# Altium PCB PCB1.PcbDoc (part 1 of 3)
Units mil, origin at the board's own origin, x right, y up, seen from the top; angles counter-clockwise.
Board outline 3586 x 4364 mil, 2 copper layers (Top Layer, Bottom Layer); 0 components, 57 nets, 205 pads, 0 vias.
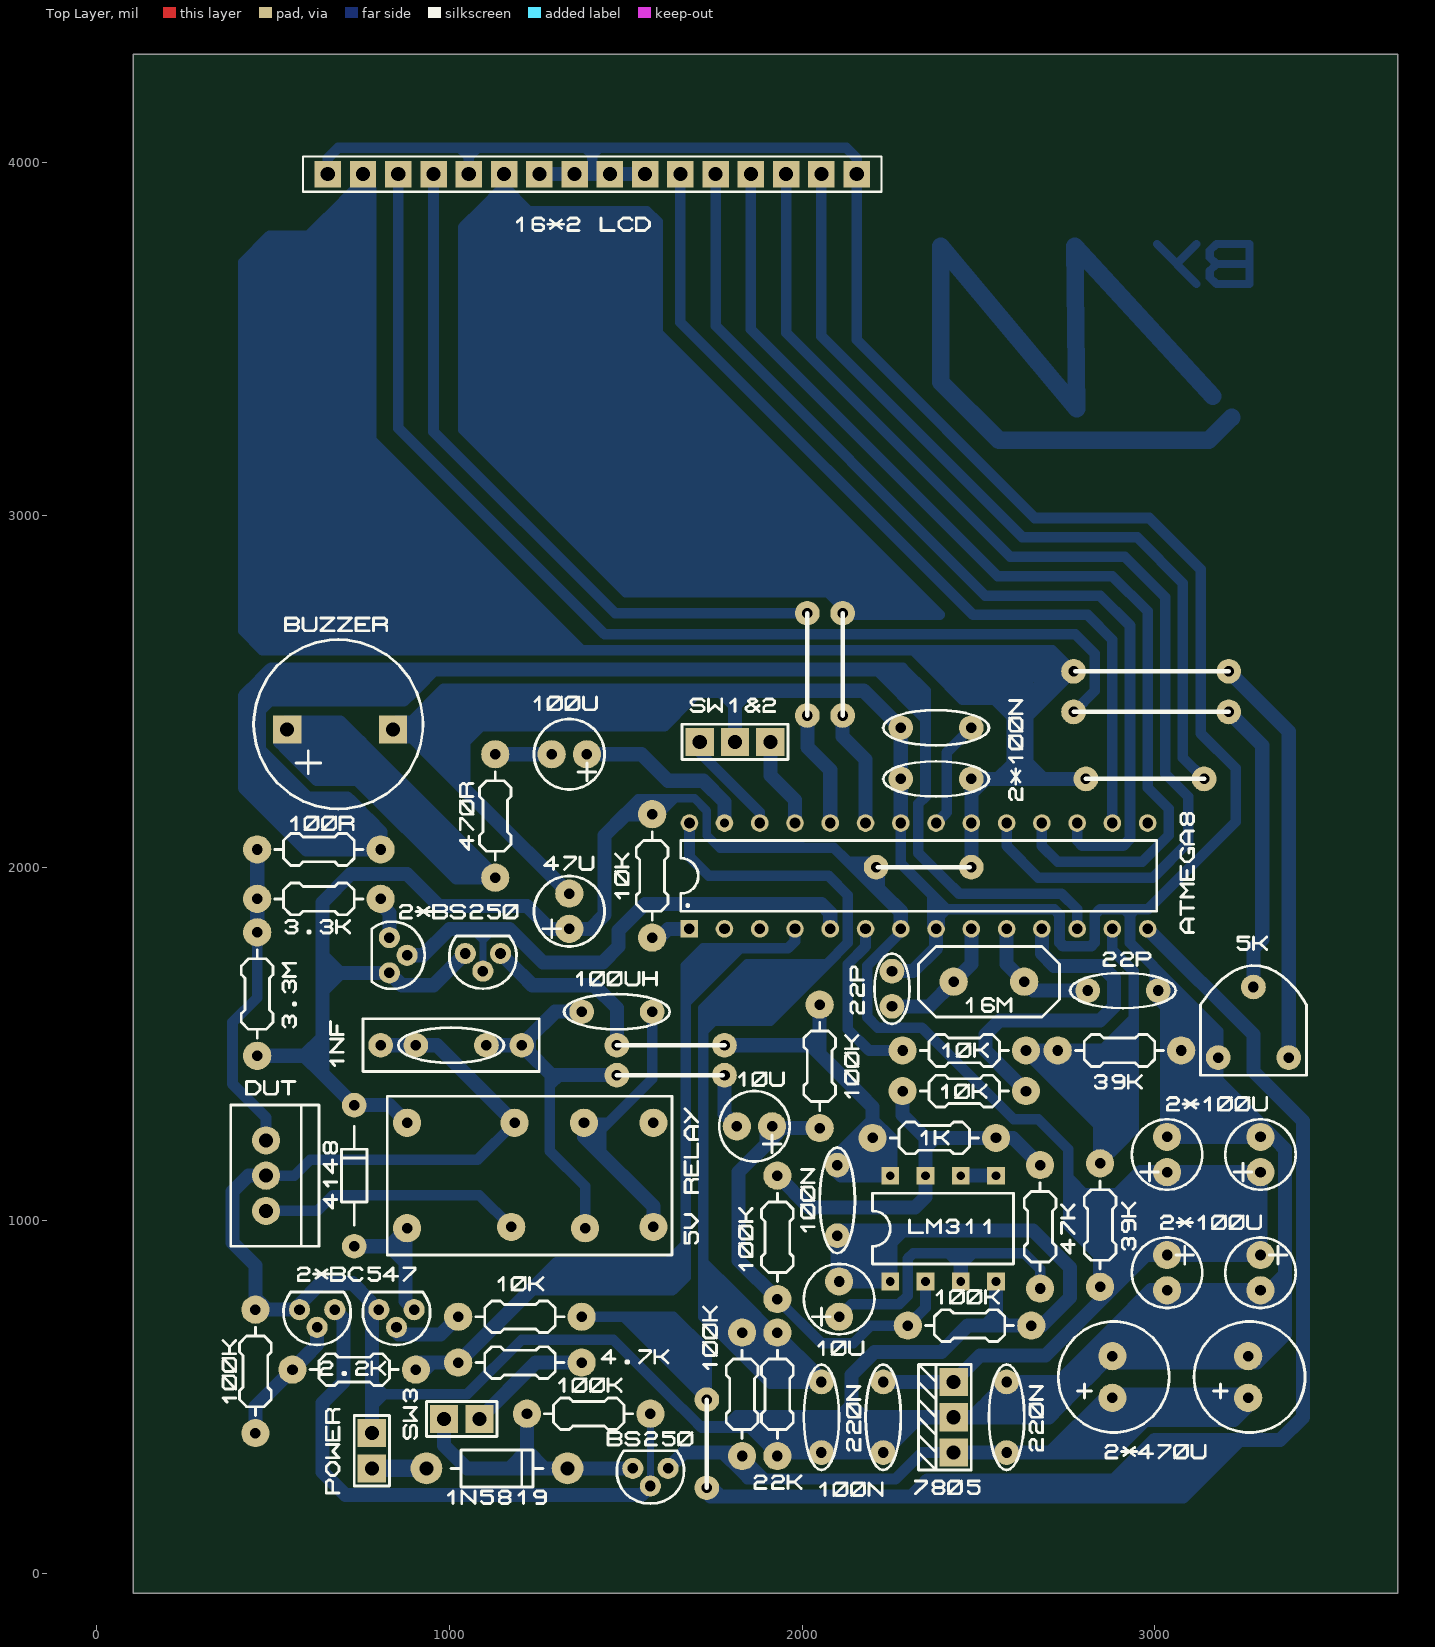
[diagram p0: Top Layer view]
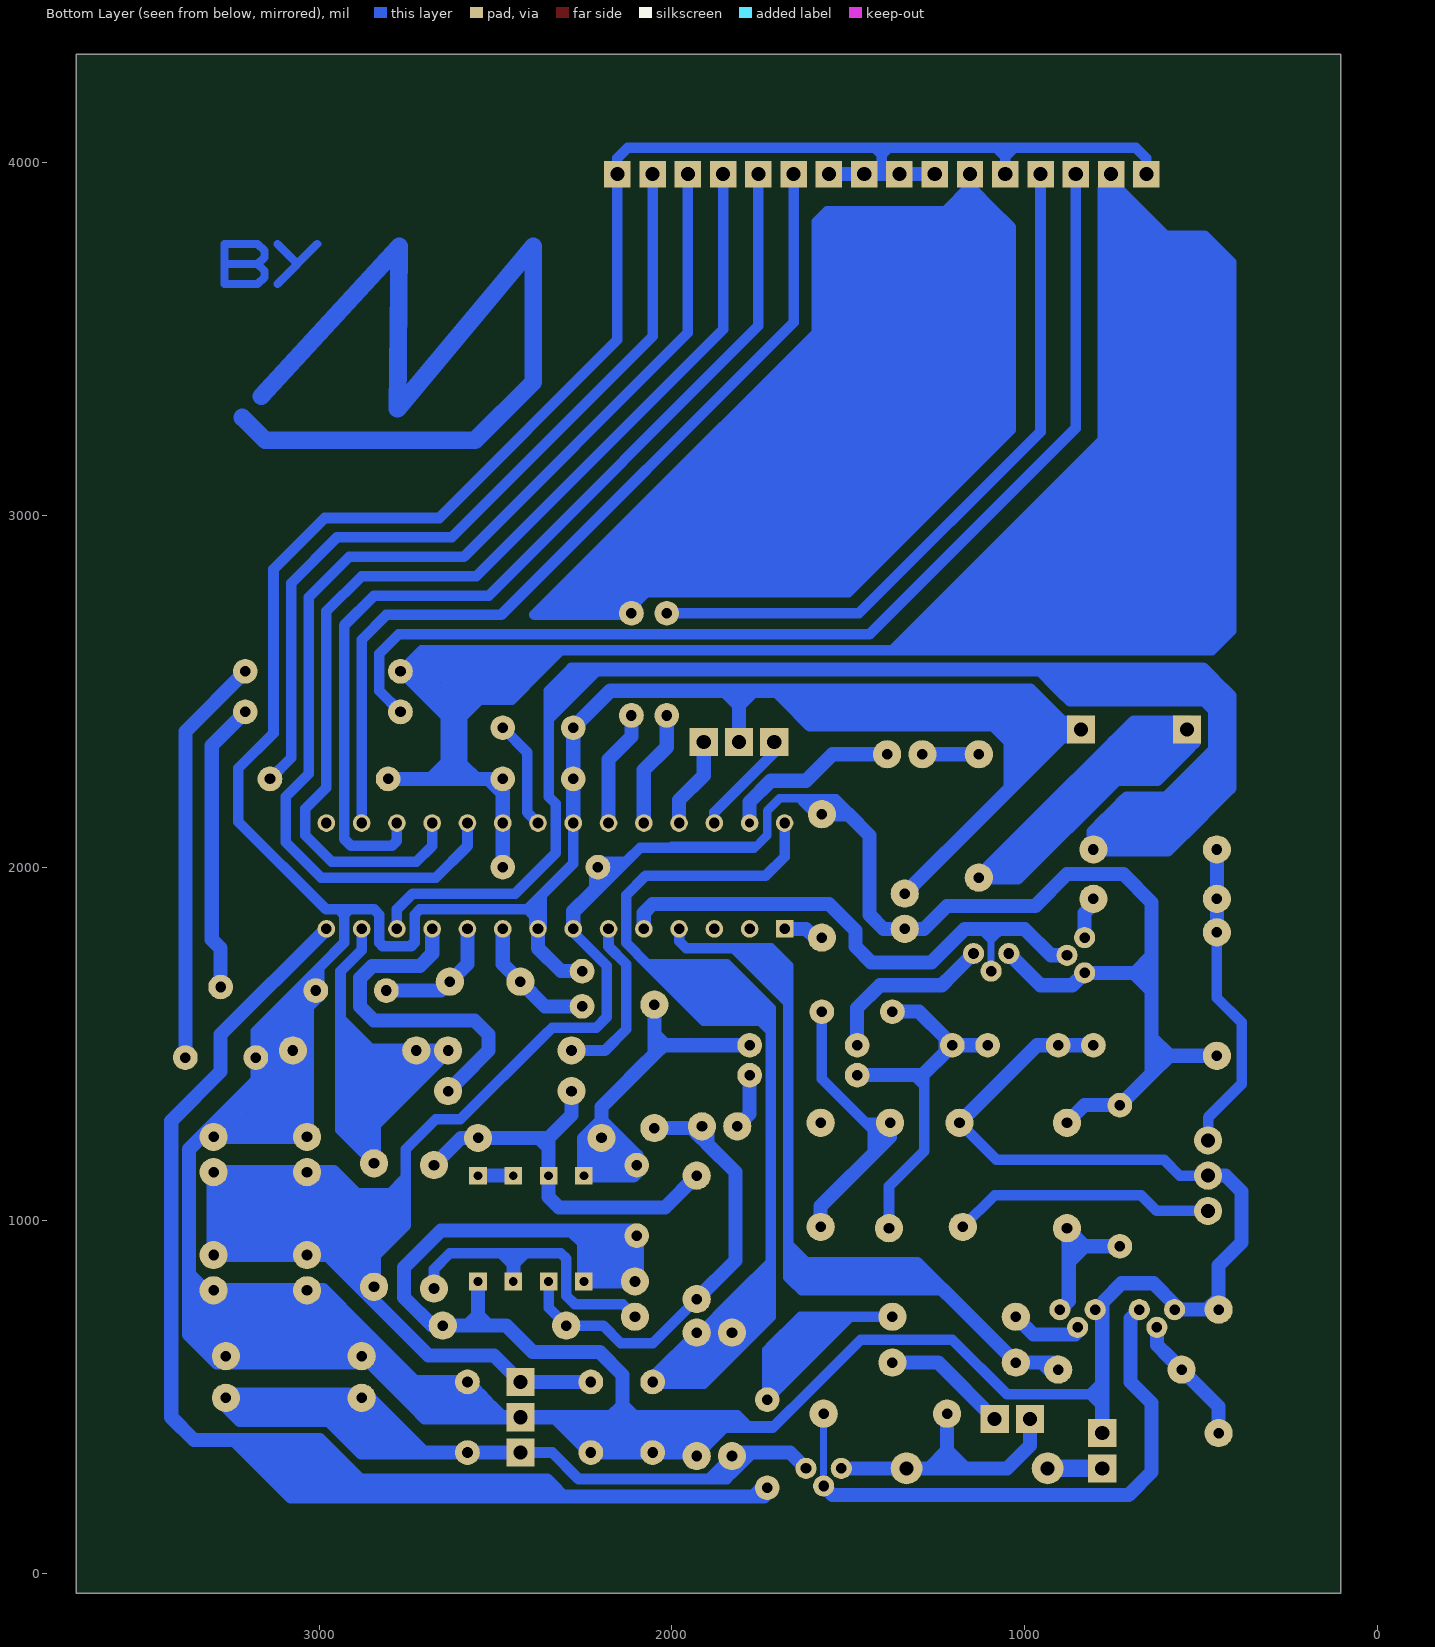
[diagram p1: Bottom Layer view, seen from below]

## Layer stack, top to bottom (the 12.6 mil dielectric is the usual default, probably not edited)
Top Layer: signal copper 1.4
Dielectric: dielectric 12.6, FR-4, Dk 4.8
Bottom Layer: signal copper 1.4

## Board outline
103,-57 3689,-57 3689,4307 103,4307

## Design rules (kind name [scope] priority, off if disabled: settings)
Clearance CAM_Clearance_2 [OnLayer('Top Layer')] p1: gap=10.71
Clearance CAM_Clearance_1 [OnLayer('Bottom Layer')] p2: gap=10
Clearance [All] p3: gap=10
PolygonConnect [All] p1: connectstyle=Relief reliefconductorwidth=10 reliefentries=4 polygonreliefangle="90 Angle"
RoutingVias [All] p1: holewidth=28 width=50 viastyle="Through Hole" minholewidth=28 minwidth=50 maxholewidth=28 maxwidth=50
SilkscreenOverComponentPads [All] p1: minsilkscreentomaskgap=10
SolderMaskExpansion [All] p1: expansion=4
Width CAM_Width_1 [OnLayer('Bottom Layer')] p1: maxlimit=101 minlimit=19 preferedwidth=20
Width [All] p2: maxlimit=10 minlimit=10 preferedwidth=10
27 further rules are at their usual default settings.

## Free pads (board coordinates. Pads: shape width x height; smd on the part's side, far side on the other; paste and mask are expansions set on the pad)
  round 60 hole 118.1: 1(0,0) 1(0,0) 1(0,0) 1(0,0)
  round 80 hole 30: 1(449.35,396.74) 1(449.35,746.74) 1(454.35,1466.74) 1(454.35,1816.74) 1(454.35,1911.74) 1(454.35,2051.74) 1(554.35,576.74) 1(804.35,1911.74) 1(804.35,2051.74) 1(879.35,977.74) 1(879.35,1276.74) 1(904.35,576.74) 1(1024.35,596.74) 1(1024.35,726.74) 1(1129.35,1971.74) 1(1129.35,2321.74) 1(1174.65,981.54) 1(1184.15,1276.74) 1(1219.35,451.74) 1(1289.35,2321.74) 1(1339.35,1826.74) 1(1339.35,1926.74) 1(1374.35,596.74) 1(1374.35,726.74) 1(1380.95,1276.74) 1(1384.15,977.74) 1(1389.35,2321.74) 1(1569.35,451.74) 1(1574.35,1801.74) 1(1574.35,2151.74) 1(1577.85,981.54) 1(1577.85,1276.74) 1(1814.35,1266.74) 1(1829.35,331.74) 1(1829.35,681.74) 1(1914.35,1266.74) 1(1929.35,331.74) 1(1929.35,681.74) 1(1929.35,776.74) 1(1929.35,1126.74) 1(2049.35,1261.74) 1(2049.35,1611.74) 1(2104.35,726.74) 1(2104.35,826.74) 1(2199.35,1233.74) 1(2284.35,1366.74) 1(2284.35,1481.74) 1(2299.35,701.74) 1(2429.35,1676.74) 1(2549.35,1233.74) 1(2629.35,1676.74) 1(2634.35,1366.74) 1(2634.35,1481.74) 1(2649.35,701.74) 1(2674.35,806.74) 1(2674.35,1156.74) 1(2724.35,1481.74) 1(2844.35,811.74) 1(2844.35,1161.74) 1(2879.35,496.74) 1(2879.35,614.94) 1(3034.35,801.74) 1(3034.35,901.74) 1(3034.35,1136.74) 1(3034.35,1236.74) 1(3074.35,1481.74) 1(3264.35,496.74) 1(3264.35,614.94) 1(3299.35,801.74) 1(3299.35,901.74) 1(3299.35,1136.74) 1(3299.35,1236.74)
  round 80 hole 40: 1(479.35,1026.74) 1(479.35,1126.74) 1(479.35,1226.74)
  rect 80x80 hole 40: 1(539.35,2391.74) 1(779.35,296.74) 1(779.35,396.74) 1(839.35,2391.74) 1(984.35,436.74) 1(1084.35,436.74) 1(1709.35,2356.74) 1(1809.35,2356.74) 1(1909.35,2356.74) 1(2429.35,341.74) 1(2429.35,441.74) 1(2429.35,541.74)
  round 60 hole 30: 1(574.35,746.74) 1(624.35,696.74) 1(674.35,746.74) 1(799.35,746.74) 1(829.35,1701.74) 1(829.35,1801.74) 1(849.35,696.74) 1(879.35,1751.74) 1(899.35,746.74) 1(1044.35,1756.74) 1(1094.35,1706.74) 1(1144.35,1756.74) 1(1519.35,296.74) 1(1569.35,246.74) 1(1619.35,296.74)
  rect 75x75 hole 40: 1(654.35,3966.74) 1(754.35,3966.74) 1(854.35,3966.74) 1(954.35,3966.74) 1(1054.35,3966.74) 1(1154.35,3966.74) 1(1254.35,3966.74) 1(1354.35,3966.74) 1(1454.35,3966.74) 1(1554.35,3966.74) 1(1654.35,3966.74) 1(1754.35,3966.74) 1(1854.35,3966.74) 1(1954.35,3966.74) 1(2054.35,3966.74) 1(2154.35,3966.74)
  round 70 hole 30: 1(729.35,926.74) 1(729.35,1326.74) 1(804.35,1496.74) 1(904.35,1496.74) 1(1104.35,1496.74) 1(1204.35,1496.74) 1(1374.35,1591.74) 1(1474.35,1411.74) 1(1474.35,1496.74) 1(1574.35,1591.74) 1(1729.35,241.74) 1(1729.35,491.74) 1(1779.35,1411.74) 1(1779.35,1496.74) 1(2014.35,2431.74) 1(2014.35,2721.74) 1(2054.35,341.74) 1(2054.35,541.74) 1(2099.35,956.74) 1(2099.35,1156.74) 1(2114.35,2431.74) 1(2114.35,2721.74) 1(2209.35,2001.74) 1(2229.35,341.74) 1(2229.35,541.74) 1(2254.35,1606.74) 1(2254.35,1706.74) 1(2279.35,2251.74) 1(2279.35,2396.74) 1(2479.35,2001.74) 1(2479.35,2251.74) 1(2479.35,2396.74) 1(2579.35,341.74) 1(2579.35,541.74) 1(2769.35,2441.74) 1(2769.35,2556.74) 1(2804.35,2251.74) 1(2809.35,1651.74) 1(3009.35,1651.74) 1(3139.35,2251.74) 1(3179.35,1461.74) 1(3209.35,2441.74) 1(3209.35,2556.74) 1(3279.35,1661.74) 1(3379.35,1461.74)
  round 90 hole 40: 1(934.35,296.74) 1(1334.35,296.74)
  rect 50x50 hole 30: 1(1679.35,1826.74)
  round 50 hole 30: 1(1680.15,2126.74) 1(1779.35,1826.74) 1(1879.35,1826.74) 1(1879.35,2126.74) 1(1979.35,1826.74) 1(1979.35,2126.74) 1(2079.35,1826.74) 1(2079.35,2126.74) 1(2179.35,1826.74) 1(2179.35,2126.74) 1(2279.35,1826.74) 1(2279.35,2126.74) 1(2379.35,1826.74) 1(2379.35,2126.74) 1(2479.35,1826.74) 1(2479.35,2126.74) 1(2579.35,1826.74) 1(2579.35,2126.74) 1(2679.35,1826.74) 1(2679.35,2126.74) 1(2779.35,1826.74) 1(2779.35,2126.74) 1(2879.35,1826.74) 1(2879.35,2126.74) 1(2979.35,1826.74) 1(2979.35,2126.74)
  round 50 hole 25: 1(1779.35,2126.74)
  rect 50x50 hole 25: 1(2249.35,826.74) 1(2249.35,1126.74) 1(2349.35,826.74) 1(2349.35,1126.74) 1(2449.35,826.74) 1(2449.35,1126.74) 1(2549.35,826.74) 1(2549.35,1126.74)

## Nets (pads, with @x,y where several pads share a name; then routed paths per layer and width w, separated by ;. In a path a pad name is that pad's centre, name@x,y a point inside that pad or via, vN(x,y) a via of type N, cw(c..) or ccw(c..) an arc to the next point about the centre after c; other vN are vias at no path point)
$Net0: pad.1@449.35,746.74 pad.1@479.35,1126.74 pad.1@574.35,746.74 pad.1@654.35,3966.74 pad.1@779.35,396.74 pad.1@799.35,746.74 pad.1@804.35,1496.74 pad.1@839.35,2391.74 pad.1@904.35,1496.74 pad.1@1054.35,3966.74 pad.1@1184.15,1276.74 pad.1@1254.35,3966.74 pad.1@1339.35,1926.74 pad.1@1354.35,3966.74 pad.1@1454.35,3966.74 pad.1@1554.35,3966.74 pad.1@1809.35,2356.74 pad.1@1929.35,331.74 pad.1@2054.35,341.74 pad.1@2099.35,956.74 pad.1@2104.35,826.74 pad.1@2154.35,3966.74 pad.1@2229.35,341.74 pad.1@2249.35,826.74 pad.1@2254.35,1706.74 pad.1@2279.35,2126.74 pad.1@2279.35,2251.74 pad.1@2279.35,2396.74 pad.1@2379.35,1826.74 pad.1@2429.35,441.74 pad.1@2549.35,826.74 pad.1@2579.35,541.74 pad.1@2649.35,701.74 pad.1@2879.35,614.94 pad.1@3009.35,1651.74 pad.1@3034.35,801.74 pad.1@3034.35,1236.74 pad.1@3074.35,1481.74 pad.1@3179.35,1461.74 pad.1@3264.35,614.94 pad.1@3299.35,801.74 pad.1@3299.35,1236.74 | length 40989.2
  Bottom Layer w20: pad.1@2364.35,1831.74 2364.35,1851.74 ; 2364.35,1926.74 2364.35,1886.74 2364.35,1851.74 ; pad.1@2379.35,1826.74 2364.35,1851.74 ; pad.1@2394.35,1831.74 2394.35,1841.74 2394.35,1856.74 2394.35,1866.74 ; 2734.35,1791.74 2744.35,1781.74 2749.35,1776.74 2754.35,1771.74 ; 2814.35,1781.74 2829.35,1796.74
  Bottom Layer w30: pad.1@449.35,746.74 449.35,786.74 489.35,746.74 494.35,741.74 ; pad.1@479.35,1126.74 559.35,1126.74 604.35,1171.74 1079.15,1171.74 pad.1@1184.15,1276.74 ; pad.1@654.35,3966.74 654.35,4011.74 671.85,4029.24 684.35,4041.74 764.35,4041.74 854.35,4041.74 1029.35,4041.74 ; 774.35,691.74 774.35,771.74 pad.1@799.35,746.74 ; 779.35,471.74 814.35,506.74 ; 779.35,541.74 814.35,506.74 ; 1024.35,2401.74 1039.35,2401.74 1054.35,2401.74 1069.35,2401.74 ; 1034.35,2366.74 1039.35,2371.74 1069.35,2401.74 ; 1039.35,2351.74 1089.35,2401.74 ; pad.1@1054.35,3966.74 1054.35,4016.74 ; 1109.35,2426.74 1114.35,2426.74 ; 1129.35,2461.74 1099.35,2431.74 1069.35,2401.74 ; 1154.35,2466.74 1119.35,2431.74 1114.35,2426.74 ; 1174.35,2436.74 1204.35,2436.74 1213.35,2436.74 1234.35,2436.74 ; 1254.35,2441.74 1284.35,2471.74 ; 1259.35,2441.74 1284.35,2441.74 ; 1259.35,2471.74 1269.35,2471.74 ; 1284.35,2421.74 1294.35,2421.74 ; 1299.35,2501.74 1269.35,2471.74 ; 1314.35,2501.74 1284.35,2471.74 ; 1334.35,2491.74 1314.35,2471.74 ; 1374.35,2501.74 1344.35,2471.74 ; pad.1@1374.35,3966.74 1404.35,3996.74 ; 1404.35,3966.74 1404.35,3996.74 ; pad.1@1434.35,3966.74 1404.35,3996.74 ; 1579.35,2501.74 1549.35,2471.74 ; 1624.35,2421.74 1499.35,2421.74 ; 1634.35,2441.74 1519.35,2441.74 ; 1661.85,2461.74 1539.35,2461.74 ; 1709.35,2501.74 1679.35,2471.74 ; 1804.35,426.74 2084.35,426.74 ; 1859.35,406.74 1874.35,391.74 ; 1859.35,416.74 1844.35,416.74 ; 1869.35,406.74 1884.35,391.74 ; 1879.35,446.74 1814.35,446.74 1784.35,416.74 ; pad.1@1934.35,326.74 pad.1@1929.35,331.74 1869.35,391.74 ; pad.1@1934.35,331.74 1929.35,336.74 1874.35,391.74 ; pad.1@1934.35,341.74 pad.1@1929.35,346.74 ; 1939.35,371.74 1979.35,371.74 ; pad.1@1954.35,336.74 pad.1@1944.35,346.74 ; 2009.35,341.74 2004.35,346.74 ; 2019.35,346.74 2004.35,346.74 ; 2039.35,381.74 2049.35,391.74 ; 2114.35,371.74 pad.1@2064.35,371.74 ; 2139.35,391.74 2084.35,391.74 ; 2139.35,446.74 2134.35,441.74 2119.35,426.74 ; 2254.35,366.74 2224.35,396.74 2204.35,416.74 2194.35,426.74 ; 2264.35,426.74 2194.35,426.74 ; pad.1@2279.35,2136.74 pad.1@2279.35,2126.74 2279.35,2011.74 2284.35,2006.74 2324.35,1966.74 2364.35,1926.74 2379.35,1911.74 ; pad.1@2379.35,1826.74 2379.35,1851.74 ; 2514.35,701.74 2549.35,736.74 ; 2549.35,701.74 2549.35,736.74 ; 2584.35,701.74 2549.35,736.74 ; 2999.35,1696.74 2999.35,1716.74 ; 3059.35,1581.74 3074.35,1566.74 3079.35,1561.74 ; 3174.35,1511.74 3044.35,1641.74 pad.1@3009.35,1651.74 3009.35,1706.74 ; 3179.35,1391.74 pad.1@3179.35,1461.74 3179.35,1481.74 3179.35,1536.74 3174.35,1541.74 3164.35,1551.74 3009.35,1706.74 ; 814.35,506.74 1049.35,506.74 1204.35,661.74 1369.35,661.74 1429.35,661.74 1464.35,661.74 1579.35,546.74 1624.35,501.74 1691.85,434.24 1709.35,416.74 ; 1029.35,4041.74 1054.35,4041.74 ; 1029.35,4041.74 1054.35,4016.74 ; 1054.35,4016.74 1054.35,4041.74 ; 1054.35,4016.74 1079.35,4041.74 ; 1054.35,4041.74 1079.35,4041.74 ; 1069.35,2401.74 1089.35,2401.74 ; 1079.35,4041.74 1084.35,4041.74 1119.35,4041.74 1154.35,4041.74 1164.35,4041.74 1184.35,4041.74 1224.35,4041.74 1384.35,4041.74 ; 1089.35,2401.74 1214.35,2401.74 1274.35,2401.74 ; 1089.35,2401.74 1114.35,2426.74 ; 1114.35,2426.74 1209.35,2426.74 1224.35,2426.74 ; 1224.35,2426.74 1229.35,2431.74 ; 1224.35,2426.74 1299.35,2426.74 ; 1229.35,2431.74 1234.35,2431.74 ; 1229.35,2431.74 1234.35,2436.74 ; 1229.35,2431.74 1209.35,2431.74 1179.35,2431.74 1169.35,2431.74 1234.35,2431.74 ; 1234.35,2431.74 1294.35,2431.74 ; 1234.35,2436.74 1269.35,2471.74 ; 1234.35,2436.74 1279.35,2436.74 ; 1269.35,2471.74 1284.35,2471.74 ; 1274.35,2401.74 1479.35,2401.74 ; 1274.35,2401.74 1294.35,2421.74 ; 1279.35,2436.74 1284.35,2441.74 ; 1279.35,2436.74 1299.35,2436.74 ; 1284.35,2441.74 1314.35,2471.74 ; 1284.35,2441.74 1304.35,2441.74 ; 1284.35,2471.74 1314.35,2471.74 ; 1294.35,2421.74 1499.35,2421.74 ; 1294.35,2421.74 1299.35,2426.74 ; 1294.35,2431.74 1299.35,2436.74 ; 1294.35,2431.74 1304.35,2431.74 ; 1299.35,2426.74 1304.35,2431.74 ; 1299.35,2436.74 1309.35,2436.74 ; 1299.35,2436.74 1304.35,2441.74 ; 1304.35,2431.74 1309.35,2436.74 ; 1304.35,2441.74 1314.35,2441.74 ; 1309.35,2436.74 1314.35,2441.74 ; 1314.35,2441.74 1519.35,2441.74 ; 1314.35,2441.74 1319.35,2446.74 1324.35,2451.74 1334.35,2461.74 ; 1314.35,2471.74 1344.35,2471.74 ; 1334.35,2461.74 1539.35,2461.74 ; 1334.35,2461.74 1344.35,2471.74 ; 1344.35,2471.74 1549.35,2471.74 ; 1384.35,4041.74 1404.35,4021.74 ; 1384.35,4041.74 1404.35,4041.74 ; 1404.35,3996.74 1404.35,4001.74 1404.35,4006.74 1404.35,4021.74 ; 1404.35,4021.74 1404.35,4041.74 ; 1404.35,4021.74 1424.35,4041.74 ; 1404.35,4041.74 1424.35,4041.74 ; 1424.35,4041.74 1454.35,4041.74 1474.35,4041.74 2009.35,4041.74 2069.35,4041.74 2124.35,4041.74 2154.35,4011.74 2154.35,3976.74 pad.1@2154.35,3966.74 2154.35,3496.74 2659.35,2991.74 2984.35,2991.74 3129.35,2846.74 3129.35,2381.74 3229.35,2281.74 3229.35,2130.74 2980.35,1881.74 2944.35,1881.74 ; 1479.35,2401.74 1594.35,2401.74 1609.35,2401.74 1679.35,2471.74 ; 1479.35,2401.74 1499.35,2421.74 ; 1499.35,2421.74 1519.35,2441.74 ; 1519.35,2441.74 1539.35,2461.74 ; 1539.35,2461.74 1549.35,2471.74 ; 1549.35,2471.74 1679.35,2471.74 ; 1709.35,416.74 1714.35,411.74 1794.35,411.74 1829.35,411.74 1844.35,411.74 ; 1709.35,416.74 1784.35,416.74 ; 1784.35,416.74 1844.35,416.74 ; 1844.35,411.74 1849.35,411.74 ; 1844.35,411.74 1844.35,416.74 ; 1844.35,416.74 1849.35,411.74 ; 1849.35,411.74 2069.35,411.74 ; 1849.35,411.74 1869.35,391.74 ; 1869.35,391.74 1874.35,391.74 ; 1874.35,391.74 1884.35,391.74 ; 1884.35,391.74 1899.35,391.74 ; 1884.35,391.74 pad.1@1924.35,351.74 ; 1899.35,391.74 1959.35,391.74 ; 1899.35,391.74 pad.1@1924.35,366.74 ; pad.1@1924.35,346.74 pad.1@1924.35,351.74 ; pad.1@1924.35,346.74 1929.35,341.74 pad.1@1929.35,346.74 ; pad.1@1924.35,346.74 pad.1@1929.35,346.74 ; pad.1@1924.35,351.74 pad.1@1924.35,366.74 ; pad.1@1924.35,351.74 pad.1@1929.35,346.74 ; pad.1@1924.35,366.74 pad.1@1944.35,346.74 ; pad.1@1929.35,346.74 pad.1@1944.35,346.74 ; pad.1@1944.35,346.74 2004.35,346.74 ; 1959.35,391.74 2049.35,391.74 ; 1959.35,391.74 1979.35,371.74 ; 1979.35,371.74 pad.1@2064.35,371.74 ; 1979.35,371.74 2004.35,346.74 ; 2049.35,391.74 2069.35,411.74 ; 2049.35,391.74 2084.35,391.74 ; pad.1@2064.35,371.74 2084.35,391.74 ; 2069.35,411.74 2084.35,426.74 ; 2084.35,391.74 2119.35,426.74 ; 2084.35,426.74 2099.35,441.74 2139.35,481.74 2179.35,441.74 2194.35,426.74 ; 2084.35,426.74 2119.35,426.74 ; 2119.35,426.74 2139.35,426.74 2194.35,426.74 ; 2379.35,1851.74 2394.35,1866.74 2409.35,1881.74 ; 2379.35,1851.74 2379.35,1881.74 ; 2379.35,1881.74 2379.35,1911.74 ; 2379.35,1881.74 2409.35,1881.74 ; 2379.35,1911.74 2389.35,1901.74 2409.35,1881.74 ; 2409.35,1881.74 2714.35,1881.74 2729.35,1866.74 2729.35,1786.74 2739.35,1776.74 2749.35,1776.74 2819.35,1776.74 2829.35,1786.74 2829.35,1796.74 2829.35,1866.74 2844.35,1881.74 2899.35,1881.74 2914.35,1881.74 ; 2914.35,1881.74 2921.85,1874.24 ; 2914.35,1881.74 2929.35,1881.74 ; 2921.85,1874.24 2929.35,1866.74 ; 2921.85,1874.24 2929.35,1881.74 ; 2929.35,1866.74 2944.35,1881.74 ; 2929.35,1866.74 2929.35,1881.74 ; 2929.35,1866.74 2929.35,1856.74 2929.35,1786.74 2994.35,1721.74 2999.35,1716.74 ; 2929.35,1881.74 2944.35,1881.74 ; 2999.35,1716.74 3009.35,1706.74
  Bottom Layer w40: pad.1@449.35,746.74 469.35,746.74 489.35,746.74 539.35,746.74 pad.1@574.35,746.74 574.35,761.74 634.35,821.74 724.35,821.74 774.35,771.74 ; 449.35,786.74 449.35,871.74 384.35,936.74 384.35,1081.74 429.35,1126.74 pad.1@479.35,1126.74 ; pad.1@779.35,391.74 pad.1@779.35,396.74 779.35,436.74 779.35,461.74 779.35,471.74 779.35,501.74 779.35,511.74 779.35,541.74 779.35,546.74 779.35,566.74 779.35,586.74 779.35,661.74 pad.1@779.35,726.74 ; pad.1@779.35,756.74 pad.1@779.35,726.74 ; pad.1@799.35,746.74 pad.1@779.35,726.74 ; pad.1@804.35,1496.74 809.35,1496.74 899.35,1496.74 pad.1@904.35,1496.74 pad.1@904.55,1496.64 ; pad.1@849.35,2411.74 894.35,2411.74 ; pad.1@884.35,1496.64 pad.1@904.55,1496.64 ; 909.35,2386.74 939.35,2386.74 ; 914.35,2411.74 894.35,2411.74 ; 959.35,2371.74 939.35,2371.74 ; 969.35,2431.74 974.35,2431.74 ; 974.35,2301.74 974.35,2386.74 ; 974.35,2456.74 974.35,2446.74 ; 1004.35,2416.74 1014.35,2426.74 ; 1014.35,2261.74 1014.35,2386.74 ; 1014.35,2481.74 1014.35,2431.74 ; 1019.35,2466.74 1039.35,2466.74 ; 1029.35,2376.74 1039.35,2386.74 ; 1029.35,2411.74 1039.35,2421.74 ; 1039.35,2236.74 1039.35,2351.74 1039.35,2371.74 1039.35,2386.74 ; 1109.35,2491.74 1084.35,2466.74 ; 1154.35,2486.74 1174.35,2466.74 ; 1159.35,2451.74 1174.35,2436.74 1179.35,2431.74 1169.35,2431.74 1119.35,2431.74 1099.35,2431.74 1084.35,2431.74 ; pad.1@1184.15,1276.74 1069.35,1391.54 964.25,1496.64 939.35,1496.64 pad.1@904.55,1496.64 ; pad.1@1254.35,3966.74 1304.35,3966.74 pad.1@1354.35,3966.74 1374.35,3966.74 1379.35,3966.74 1404.35,3966.74 1424.35,3966.74 1429.35,3966.74 1434.35,3966.74 pad.1@1454.35,3966.74 pad.1@1554.35,3966.74 ; 1284.35,2496.74 1229.35,2456.74 ; pad.1@1339.35,1926.74 1244.35,2021.74 1194.35,2071.74 994.35,2271.74 ; pad.1@1809.35,2356.74 1809.35,2461.74 ; 1879.35,441.74 2099.35,441.74 2126.85,441.74 2134.35,441.74 2139.35,441.74 ; pad.1@1929.35,336.74 pad.1@1929.35,341.74 ; pad.1@1929.35,361.74 pad.1@1929.35,331.74 1964.35,366.74 1969.35,366.74 ; 1969.35,341.74 1999.35,341.74 2009.35,341.74 2019.35,341.74 pad.1@2054.35,341.74 2079.35,341.74 2139.35,341.74 ; pad.1@2099.35,831.74 2099.35,901.74 ; pad.1@2099.35,971.74 2284.35,971.74 ; 2104.35,346.74 2139.35,381.74 ; pad.1@2109.35,811.74 pad.1@2124.35,826.74 ; 2109.35,911.74 2149.35,911.74 ; 2114.35,396.74 2139.35,396.74 ; pad.1@2114.35,826.74 pad.1@2124.35,826.74 ; 2124.35,416.74 2139.35,416.74 ; 2134.35,366.74 2139.35,366.74 ; 2140.35,846.74 2144.35,846.74 ; 2174.35,346.74 2154.35,366.74 ; 2179.35,891.74 2184.35,886.74 ; 2194.35,896.74 2184.35,886.74 ; 2199.35,861.74 2181.85,879.24 ; 2234.35,879.24 2191.85,879.24 ; 2234.35,911.74 2149.35,911.74 ; pad.1@2249.35,366.74 2154.35,366.74 ; pad.1@2254.35,1706.74 2314.35,1706.74 2379.35,1771.74 pad.1@2379.35,1826.74 ; 2261.85,956.74 2249.35,956.74 ; pad.1@2279.35,2136.74 pad.1@2279.35,2251.74 pad.1@2279.35,2396.74 2174.35,2501.74 1849.35,2501.74 ; 2281.85,396.74 2224.35,396.74 2139.35,396.74 ; 2289.35,416.74 2204.35,416.74 2139.35,416.74 ; 2484.35,443.54 2547.55,506.74 2547.55,506.84 ; 2525.95,485.14 2547.55,506.84 ; 2549.35,736.74 pad.1@2549.35,826.74 ; 2554.35,471.74 2679.35,471.74 2729.35,471.74 ; 2554.35,486.74 2529.35,461.74 ; 2554.35,506.74 pad.1@2571.15,530.44 ; 2559.35,461.74 2529.35,461.74 ; 2584.35,490.84 2719.35,490.84 ; pad.1@2584.35,543.54 pad.1@2582.55,541.74 ; 2614.35,521.74 2709.35,521.74 ; 2767.25,541.74 2729.35,541.74 ; 2769.35,536.74 2829.35,596.74 ; pad.1@2859.35,630.84 2750.25,521.74 ; 2919.35,601.74 2932.45,614.94 ; 2959.35,601.74 2972.45,614.94 ; pad.1@2999.35,1641.74 3024.35,1616.74 ; 3004.35,601.74 3017.45,614.94 ; 3004.35,644.24 3001.85,644.24 ; pad.1@3004.35,1646.74 3004.35,1686.74 ; 3004.35,1704.24 3004.35,1691.74 3004.35,1686.74 ; pad.1@3014.35,781.74 2929.35,696.74 ; pad.1@3034.35,781.74 pad.1@3034.35,801.74 ; 3034.35,1621.74 3034.35,1606.74 ; 3046.85,696.74 3014.35,696.74 ; pad.1@3047.45,801.74 pad.1@3034.35,801.74 ; 3059.35,1276.74 3059.35,1321.74 ; 3066.85,671.74 3029.35,671.74 ; pad.1@3074.35,1491.74 3074.35,1531.74 3074.35,1566.74 3074.35,1586.74 ; 3074.35,1521.74 pad.1@3074.35,1481.74 3074.35,1366.74 3074.35,1341.74 ; 3079.35,1561.74 pad.1@3179.35,1461.74 ; 3094.35,1411.74 3094.35,1341.74 ; 3094.35,1521.74 3109.35,1506.74 ; 3109.35,1516.74 3109.35,1506.74 ; 3114.35,1306.74 3134.35,1306.74 ; 3124.35,606.74 3132.45,614.94 ; 3124.35,1386.74 3124.35,1341.74 ; 3134.35,1266.74 3134.35,1281.74 ; 3134.35,1496.74 3134.35,1481.74 ; 3139.35,1491.74 3139.35,1476.74 ; 3149.35,791.74 3105.85,748.34 ; 3149.35,1426.74 pad.1@3179.35,1461.74 ; 3159.35,1361.74 3134.35,1336.74 ; 3159.35,1411.74 3164.35,1406.74 ; 3164.35,601.74 3177.45,614.94 ; 3164.35,1321.74 3149.35,1321.74 ; pad.1@3164.35,1451.74 3139.35,1476.74 ; 3174.35,1341.74 3164.35,1341.74 3164.35,1371.74 ; pad.1@3179.35,1481.74 3074.35,1586.74 ; 3184.35,1306.74 3179.35,1306.74 ; 3199.35,796.74 3128.35,725.84 ; 3204.35,1266.74 3189.35,1281.74 ; 3209.35,606.74 3217.45,614.94 ; 3234.35,791.74 3148.35,705.84 ; 3239.35,716.74 3264.35,741.74 ; 3251.85,1281.74 3189.35,1281.74 ; pad.1@3254.35,651.74 pad.1@3228.35,625.84 ; 3254.35,691.74 3208.35,645.84 ; 3254.35,766.74 3170.85,683.34 ; 3259.35,671.74 3264.35,676.74 ; 3339.35,681.74 3339.35,751.74 ; 3339.35,801.74 3339.35,751.74 ; 3354.35,766.74 3339.35,751.74 ; pad.1@874.35,2391.74 894.35,2371.74 ; pad.1@874.35,2391.74 894.35,2411.74 ; pad.1@874.35,2391.74 pad.1@839.35,2391.74 879.35,2371.74 894.35,2371.74 ; pad.1@874.35,2391.74 939.35,2391.74 ; 894.35,2371.74 939.35,2326.74 ; 894.35,2371.74 939.35,2371.74 ; 894.35,2411.74 984.35,2501.74 1029.35,2501.74 ; 939.35,2326.74 939.35,2371.74 ; 939.35,2326.74 954.35,2311.74 994.35,2271.74 ; 939.35,2371.74 939.35,2386.74 ; 939.35,2386.74 939.35,2391.74 ; 939.35,2386.74 974.35,2386.74 ; 939.35,2391.74 939.35,2411.74 974.35,2446.74 ; 974.35,2386.74 974.35,2431.74 ; 974.35,2386.74 994.35,2386.74 ; 974.35,2431.74 974.35,2446.74 ; 974.35,2431.74 994.35,2431.74 ; 974.35,2446.74 994.35,2466.74 ; 994.35,2271.74 994.35,2386.74 ; 994.35,2386.74 994.35,2431.74 ; 994.35,2386.74 1014.35,2386.74 ; 994.35,2431.74 994.35,2466.74 ; 994.35,2431.74 1014.35,2431.74 ; 994.35,2466.74 1029.35,2501.74 ; 1014.35,2386.74 1014.35,2426.74 ; 1014.35,2386.74 1039.35,2386.74 ; 1014.35,2426.74 1014.35,2431.74 ; 1014.35,2426.74 1019.35,2431.74 ; 1014.35,2431.74 1019.35,2431.74 ; 1019.35,2431.74 1039.35,2451.74 ; 1019.35,2431.74 1039.35,2431.74 ; 1029.35,2501.74 1039.35,2501.74 ; 1039.35,2386.74 1054.35,2401.74 1084.35,2431.74 ; 1039.35,2386.74 1039.35,2401.74 1039.35,2421.74 ; 1039.35,2421.74 1049.35,2431.74 ; 1039.35,2421.74 1039.35,2431.74 ; 1039.35,2431.74 1039.35,2451.74 ; 1039.35,2431.74 1049.35,2431.74 ; 1039.35,2451.74 1039.35,2466.74 ; 1039.35,2451.74 1054.35,2466.74 ; 1039.35,2466.74 1039.35,2501.74 ; 1039.35,2466.74 1054.35,2466.74 ; 1039.35,2501.74 1089.35,2501.74 ; 1049.35,2431.74 1084.35,2466.74 ; 1049.35,2431.74 1084.35,2431.74 ; 1054.35,2466.74 1089.35,2501.74 ; 1054.35,2466.74 1084.35,2466.74 ; 1084.35,2431.74 1119.35,2466.74 ; 1084.35,2466.74 1119.35,2466.74 ; 1089.35,2501.74 1119.35,2501.74 1124.35,2501.74 1139.35,2501.74 1154.35,2501.74 ; 1119.35,2466.74 1154.35,2466.74 1174.35,2466.74 ; 1119.35,2466.74 1154.35,2501.74 ; 1154.35,2501.74 1179.35,2501.74 ; 1174.35,2466.74 1204.35,2436.74 1209.35,2431.74 1213.35,2436.74 1229.35,2456.74 ; 1174.35,2466.74 1214.35,2466.74 ; 1179.35,2501.74 1214.35,2501.74 ; 1179.35,2501.74 1214.35,2466.74 ; 1214.35,2466.74 1229.35,2456.74 ; 1214.35,2466.74 1214.35,2501.74 ; 1214.35,2466.74 1249.35,2501.74 ; 1214.35,2501.74 1249.35,2501.74 ; 1249.35,2501.74 1299.35,2501.74 1314.35,2501.74 1374.35,2501.74 1509.35,2501.74 1519.35,2501.74 1579.35,2501.74 1709.35,2501.74 1769.35,2501.74 ; 1769.35,2501.74 1804.35,2501.74 ; 1769.35,2501.74 1804.35,2466.74 ; 1804.35,2466.74 1809.35,2466.74 1809.35,2461.74 ; 1804.35,2466.74 1804.35,2501.74 ; 1804.35,2466.74 1839.35,2501.74 ; 1804.35,2501.74 1839.35,2501.74 ; 1809.35,2461.74 1849.35,2501.74 ; 1839.35,2501.74 1849.35,2501.74 ; 2099.35,901.74 2121.85,879.24 ; 2099.35,901.74 2099.35,916.74 2099.35,921.74 pad.1@2099.35,956.74 ; pad.1@2099.35,956.74 2249.35,956.74 ; pad.1@2099.35,956.74 2129.05,931.34 ; 2121.85,879.24 2176.85,879.24 ; 2121.85,879.24 2149.35,851.74 ; pad.1@2124.35,826.74 2144.35,846.74 ; pad.1@2124.35,826.74 2149.35,826.74 ; 2129.05,931.34 2134.35,926.74 2149.35,911.74 ; 2129.05,931.34 2249.35,931.34 ; 2139.35,341.74 2139.35,366.74 ; 2139.35,341.74 2224.35,341.74 pad.1@2229.35,341.74 2254.35,366.74 2329.35,441.74 ; 2139.35,366.74 2139.35,381.74 ; 2139.35,366.74 2154.35,366.74 ; 2139.35,381.74 2154.35,366.74 ; 2139.35,381.74 2139.35,391.74 2139.35,396.74 ; 2139.35,396.74 2139.35,416.74 ; 2139.35,416.74 2139.35,426.74 2139.35,441.74 ; 2139.35,441.74 2179.35,441.74 2199.35,441.74 2329.35,441.74 ; 2139.35,441.74 2139.35,446.74 2139.35,481.74 2139.35,501.74 2139.35,561.74 2204.35,626.74 2394.35,626.74 2469.35,701.74 2514.35,701.74 2549.35,701.74 2584.35,701.74 pad.1@2649.35,701.74 2679.35,701.74 2759.35,781.74 2759.35,866.74 2654.35,971.74 2294.35,971.74 2284.35,971.74 ; 2144.35,846.74 2149.35,846.74 ; 2144.35,846.74 2149.35,851.74 ; 2144.35,846.74 pad.1@2104.35,826.74 2104.35,851.74 2149.35,851.74 ; 2149.35,826.74 2149.35,846.74 ; 2149.35,826.74 2194.35,826.74 pad.1@2249.35,826.74 ; 2149.35,846.74 2149.35,851.74 ; 2149.35,846.74 pad.1@2224.35,846.74 ; 2149.35,851.74 2159.35,861.74 2176.85,879.24 ; 2149.35,911.74 2179.35,881.74 ; 2176.85,879.24 2179.35,881.74 ; 2176.85,879.24 2181.85,879.24 ; 2179.35,881.74 2184.35,886.74 ; 2179.35,881.74 2181.85,879.24 ; 2181.85,879.24 2191.85,879.24 ; 2184.35,886.74 2191.85,879.24 ; 2191.85,879.24 pad.1@2224.35,846.74 ; pad.1@2224.35,846.74 pad.1@2249.35,826.74 ; pad.1@2249.35,826.74 2249.35,906.34 2249.35,931.34 ; 2249.35,931.34 2249.35,936.74 ; 2249.35,936.74 2284.35,971.74 ; 2249.35,936.74 2249.35,956.74 ; 2329.35,441.74 2354.35,441.74 2389.35,441.74 pad.1@2429.35,441.74 2509.35,441.74 ; 2509.35,441.74 2519.35,441.74 2699.35,441.74 2729.35,471.74 ; 2509.35,441.74 2529.35,461.74 ; 2547.55,506.84 pad.1@2579.35,541.74 ; 2547.55,506.84 pad.1@2571.15,530.44 ; pad.1@2571.15,530.44 pad.1@2579.35,541.74 ; pad.1@2571.15,530.44 pad.1@2582.55,541.74 ; pad.1@2579.35,541.74 pad.1@2582.55,541.74 ; pad.1@2582.55,541.74 2729.35,541.74 ; 2709.35,521.74 2729.35,541.74 ; 2709.35,521.74 2750.25,521.74 ; 2719.35,490.84 2748.35,490.84 ; 2719.35,490.84 2750.25,521.74 ; 2729.35,471.74 2748.35,490.84 ; 2729.35,541.74 2884.35,696.74 ; 2748.35,490.84 2779.35,521.74 ; 2750.25,521.74 2779.35,521.74 ; 2779.35,521.74 2799.35,541.74 2809.35,551.74 pad.1@2854.35,596.74 ; 2829.35,596.74 2929.35,696.74 ; 2829.35,596.74 pad.1@2854.35,596.74 ; pad.1@2854.35,596.74 2929.35,671.74 ; pad.1@2854.35,596.74 pad.1@2861.15,596.74 ; pad.1@2861.15,596.74 3039.35,596.74 ; pad.1@2861.15,596.74 pad.1@2879.35,614.94 ; pad.1@2879.35,614.94 2936.15,671.74 ; pad.1@2879.35,614.94 2919.35,644.24 2961.85,644.24 ; 2884.35,696.74 2989.35,801.74 pad.1@3034.35,801.74 ; 2884.35,696.74 2929.35,696.74 ; 2929.35,671.74 2954.35,696.74 ; 2929.35,671.74 2936.15,671.74 ; 2929.35,696.74 2954.35,696.74 ; 2932.45,614.94 2961.85,644.24 ; 2932.45,614.94 2972.45,614.94 ; 2936.15,671.74 2961.15,696.74 ; 2936.15,671.74 2989.35,671.74 ; 2954.35,696.74 2961.15,696.74 ; 2954.35,696.74 3039.35,781.74 3039.35,749.94 ; 2961.15,696.74 2986.15,696.74 ; 2961.15,696.74 2986.15,721.74 2986.15,696.74 ; 2961.85,644.24 2989.35,671.74 ; 2961.85,644.24 3001.85,644.24 ; 2972.45,614.94 3001.85,644.24 ; 2972.45,614.94 3017.45,614.94 ; 2986.15,696.74 3007.75,718.34 3039.35,749.94 ; 2986.15,696.74 3014.35,696.74 ; 2989.35,671.74 3014.35,696.74 ; 2989.35,671.74 3029.35,671.74 ; 3001.85,644.24 3029.35,671.74 ; 3004.35,1686.74 pad.1@3009.35,1651.74 ; pad.1@3009.35,1651.74 3024.35,1616.74 ; pad.1@3009.35,1651.74 3061.85,1599.24 3074.35,1586.74 ; 3014.35,696.74 3085.85,768.34 ; 3017.45,614.94 3128.35,725.84 ; 3017.45,614.94 3057.45,614.94 ; 3024.35,1616.74 3034.35,1606.74 ; 3029.35,671.74 3105.85,748.34 ; pad.1@3034.35,1236.74 3034.35,1321.74 ; pad.1@3034.35,1236.74 3074.35,1276.74 ; pad.1@3034.35,1236.74 3074.35,1236.74 ; 3034.35,1321.74 3034.35,1606.74 ; 3034.35,1321.74 3059.35,1321.74 ; 3034.35,1606.74 3039.35,1601.74 3054.35,1586.74 3059.35,1581.74 3059.35,1321.74 ; 3039.35,596.74 3084.35,596.74 ; 3039.35,596.74 3057.45,614.94 ; 3039.35,749.94 3071.85,782.44 ; 3057.45,614.94 3148.35,705.84 ; 3057.45,614.94 3102.45,614.94 ; 3059.35,1321.74 3074.35,1321.74 ; 3071.85,782.44 3091.15,801.74 ; 3071.85,782.44 3052.45,801.74 3091.15,801.74 ; 3071.85,782.44 3085.85,768.34 ; 3074.35,1236.74 3074.35,1256.74 ; 3074.35,1236.74 pad.1@3299.35,1236.74 ; 3074.35,1256.74 3074.35,1276.74 ; 3074.35,1256.74 3179.35,1256.74 ; 3074.35,1276.74 3074.35,1321.74 ; 3074.35,1276.74 3079.35,1281.74 ; 3074.35,1321.74 3074.35,1341.74 ; 3074.35,1321.74 3119.35,1321.74 ; 3074.35,1341.74 3094.35,1341.74 ; 3079.35,1281.74 3119.35,1321.74 ; 3079.35,1281.74 3134.35,1281.74 ; 3084.35,596.74 3154.35,596.74 3179.35,596.74 3224.35,596.74 ; 3084.35,596.74 3102.45,614.94 ; 3085.85,768.34 3119.35,801.74 ; 3085.85,768.34 3105.85,748.34 ; 3091.15,801.74 3119.35,801.74 ; 3094.35,1341.74 3109.35,1341.74 ; 3102.45,614.94 3170.85,683.34 ; 3102.45,614.94 3132.45,614.94 ; 3105.85,748.34 3128.35,725.84 ; 3109.35,1341.74 3109.35,1506.74 ; 3109.35,1341.74 3124.35,1341.74 ; 3109.35,1506.74 3134.35,1481.74 ; 3119.35,801.74 3144.35,801.74 3154.35,801.74 3224.35,801.74 3259.35,801.74 3284.35,801.74 pad.1@3299.35,801.74 ; 3119.35,1321.74 3134.35,1336.74 ; 3119.35,1321.74 3134.35,1321.74 ; 3124.35,1341.74 3134.35,1341.74 ; 3128.35,725.84 3148.35,705.84 ; 3132.45,614.94 3185.85,668.34 ; 3132.45,614.94 3177.45,614.94 ; 3134.35,1281.74 3179.35,1281.74 ; 3134.35,1281.74 3134.35,1306.74 ; 3134.35,1306.74 3134.35,1321.74 ; 3134.35,1306.74 3164.35,1306.74 ; 3134.35,1321.74 3134.35,1336.74 ; 3134.35,1321.74 3149.35,1321.74 ; 3134.35,1336.74 3149.35,1321.74 ; 3134.35,1336.74 3134.35,1341.74 ; 3134.35,1341.74 3134.35,1351.74 3134.35,1401.74 ; 3134.35,1401.74 3134.35,1481.74 ; 3134.35,1401.74 3164.35,1371.74 ; 3134.35,1481.74 3139.35,1476.74 ; 3148.35,705.84 3170.85,683.34 ; 3149.35,1321.74 3164.35,1306.74 ; 3164.35,1306.74 3179.35,1306.74 ; 3164.35,1306.74 3179.35,1291.74 ; 3164.35,1371.74 3164.35,1406.74 ; 3164.35,1371.74 3179.35,1356.74 ; 3164.35,1406.74 3164.35,1426.74 pad.1@3179.35,1461.74 ; 3164.35,1406.74 3179.35,1391.74 ; 3170.85,683.34 3185.85,668.34 ; 3177.45,614.94 3208.35,645.84 ; 3177.45,614.94 3217.45,614.94 ; 3179.35,1256.74 3179.35,1281.74 ; 3179.35,1256.74 3259.35,1256.74 pad.1@3299.35,1236.74 ; 3179.35,1281.74 3179.35,1291.74 ; 3179.35,1281.74 3189.35,1281.74 ; 3179.35,1291.74 3179.35,1306.74 ; 3179.35,1291.74 3189.35,1281.74 ; 3179.35,1306.74 3179.35,1356.74 ; 3179.35,1356.74 3179.35,1391.74 ; 3179.35,1356.74 pad.1@3299.35,1236.74 ; 3179.35,1391.74 pad.1@3334.35,1236.74 ; 3185.85,668.34 3231.85,714.24 3259.35,741.74 3264.35,746.74 ; 3185.85,668.34 3208.35,645.84 ; 3208.35,645.84 pad.1@3228.35,625.84 ; 3217.45,614.94 pad.1@3228.35,625.84 ; 3217.45,614.94 pad.1@3239.35,614.94 ; 3224.35,596.74 pad.1@3269.35,596.74 ; 3224.35,596.74 pad.1@3264.35,614.94 ; pad.1@3228.35,625.84 pad.1@3239.35,614.94 ; pad.1@3239.35,614.94 pad.1@3264.35,614.94 ; pad.1@3264.35,614.94 3264.35,676.74 ; pad.1@3264.35,614.94 pad.1@3299.35,629.64 ; pad.1@3264.35,614.94 3299.35,649.94 ; pad.1@3264.35,614.94 pad.1@3269.35,596.74 ; 3264.35,676.74 3264.35,741.74 ; 3264.35,676.74 3299.35,711.74 ; 3264.35,741.74 3264.35,746.74 ; 3264.35,741.74 3269.35,746.74 ; 3264.35,746.74 3269.35,746.74 ; 3264.35,746.74 3284.35,766.74 3284.35,761.74 ; pad.1@3269.35,596.74 3289.35,596.74 3369.35,676.74 3369.35,696.74 ; pad.1@3269.35,596.74 3299.35,626.74 pad.1@3299.35,629.64 ; 3269.35,746.74 3284.35,746.74 3284.35,761.74 ; 3269.35,746.74 3284.35,761.74 ; 3284.35,761.74 pad.1@3299.35,776.74 ; pad.1@3299.35,629.64 3299.35,649.94 ; pad.1@3299.35,629.64 3304.35,631.74 3369.35,696.74 ; 3299.35,649.94 3299.35,651.74 3299.35,701.74 3299.35,711.74 ; 3299.35,711.74 3299.35,716.74 3299.35,766.74 pad.1@3299.35,776.74 ; 3299.35,711.74 3339.35,751.74 ; pad.1@3299.35,776.74 pad.1@3299.35,801.74 ; pad.1@3299.35,776.74 pad.1@3324.35,801.74 ; pad.1@3299.35,801.74 3304.35,801.74 pad.1@3324.35,801.74 ; pad.1@3299.35,1236.74 pad.1@3334.35,1236.74 ; pad.1@3324.35,801.74 3354.35,831.74 3369.35,846.74 ; pad.1@3334.35,1236.74 3344.35,1226.74 3369.35,1201.74 3369.35,1096.74 3369.35,1066.74 3369.35,926.74 3369.35,866.74 3369.35,856.74 3369.35,846.74 ; 3369.35,696.74 3369.35,731.74 3369.35,846.74
$Net1: pad.1@779.35,296.74 pad.1@934.35,296.74 | length 155
  Bottom Layer w50: pad.1@779.35,296.74 pad.1@934.35,296.74
$Net2: pad.1@984.35,436.74 pad.1@1219.35,451.74 pad.1@1334.35,296.74 pad.1@1519.35,296.74 | length 967.5
  Bottom Layer w30: pad.1@1209.35,441.74 pad.1@1219.35,451.74
  Bottom Layer w40: pad.1@984.35,436.74 984.35,361.74 1049.35,296.74 1164.35,296.74 1169.35,296.74 ; pad.1@1199.35,451.74 pad.1@1219.35,451.74 1219.35,346.74 ; pad.1@1519.35,296.74 pad.1@1334.35,296.74 1274.35,296.74 1269.35,296.74 ; 1169.35,296.74 1184.35,296.74 1209.35,296.74 1214.35,296.74 1219.35,296.74 ; 1169.35,296.74 1219.35,346.74 ; 1219.35,296.74 1219.35,346.74 ; 1219.35,296.74 1229.35,296.74 1254.35,296.74 1269.35,296.74 ; 1219.35,346.74 1269.35,296.74
$Net3: pad.1@1084.35,436.74 pad.1@1374.35,596.74 | length 356.3
  Bottom Layer w40: pad.1@1084.35,436.74 1244.35,596.74 1334.35,596.74 pad.1@1374.35,596.74
$Net4: pad.1@1619.35,296.74 pad.1@1829.35,331.74 pad.1@2429.35,341.74 pad.1@2579.35,341.74 pad.1@2879.35,496.74 pad.1@3264.35,496.74 | length 4951.5
  Bottom Layer w30: 1764.35,346.74 1769.35,341.74 1829.35,281.74 ; 1869.35,271.74 1849.35,291.74 pad.1@1829.35,331.74 ; 2254.35,266.74 2264.35,266.74 ; pad.1@2429.35,341.74 2399.35,341.74 2389.35,341.74 2369.35,341.74 2339.35,341.74 2264.35,266.74 ; 1829.35,281.74 pad.1@1829.35,331.74 ; 1829.35,281.74 1834.35,276.74 1844.35,266.74 1894.35,266.74 ; pad.1@1829.35,331.74 1894.35,266.74 ; 1894.35,266.74 2264.35,266.74
  Bottom Layer w40: pad.1@1619.35,296.74 1664.35,341.74 1709.35,341.74 1729.35,341.74 1769.35,341.74 pad.1@1819.35,341.74 ; pad.1@1829.35,331.74 pad.1@1819.35,341.74 ; pad.1@1844.35,341.74 pad.1@1819.35,341.74 ; pad.1@2429.35,341.74 2469.35,341.74 2489.35,341.74 2499.35,341.74 2534.35,341.74 2559.35,341.74 pad.1@2579.35,341.74 2694.35,341.74 2704.35,341.74 ; pad.1@2859.35,496.74 2704.35,341.74 ; pad.1@2874.35,506.74 2919.35,506.74 ; pad.1@2881.85,479.24 pad.1@2879.35,476.74 ; 2914.35,476.74 2879.35,441.74 ; 2954.35,446.74 2941.85,434.24 ; 2954.35,451.74 2936.85,434.24 ; 2954.35,466.74 2994.35,466.74 ; 2984.35,446.74 2971.85,434.24 ; 2999.35,471.74 2994.35,466.74 ; 3214.35,466.74 3121.85,466.74 ; pad.1@3264.35,476.74 pad.1@3264.35,496.74 ; pad.1@3269.35,506.74 2999.35,506.74 2919.35,506.74 ; 2704.35,341.74 2729.35,341.74 2744.35,341.74 ; 2744.35,341.74 2779.35,341.74 ; 2744.35,341.74 pad.1@2879.35,476.74 ; 2779.35,341.74 2784.35,341.74 2809.35,341.74 ; 2779.35,341.74 2871.85,434.24 ; 2809.35,341.74 2829.35,341.74 2849.35,341.74 ; 2809.35,341.74 2854.35,386.74 2879.35,411.74 ; 2849.35,341.74 2859.35,341.74 2869.35,341.74 ; 2849.35,341.74 2941.85,434.24 ; 2869.35,341.74 2961.85,434.24 ; 2869.35,341.74 2879.35,341.74 2971.85,434.24 ; 2871.85,434.24 2879.35,441.74 ; 2871.85,434.24 2879.35,434.24 ; 2879.35,411.74 2879.35,434.24 ; 2879.35,411.74 2901.85,434.24 ; 2879.35,434.24 2879.35,441.74 ; 2879.35,434.24 2901.85,434.24 ; 2879.35,441.74 2879.35,446.74 ; 2879.35,446.74 pad.1@2879.35,476.74 ; 2879.35,446.74 2929.35,496.74 ; pad.1@2879.35,476.74 pad.1@2879.35,496.74 ; pad.1@2879.35,496.74 2919.35,506.74 ; pad.1@2879.35,496.74 2929.35,496.74 ; 2901.85,434.24 2936.85,434.24 ; 2901.85,434.24 2924.35,456.74 2939.35,471.74 ; 2929.35,496.74 2939.35,496.74 ; 2936.85,434.24 2941.85,434.24 ; 2939.35,471.74 2939.35,496.74 ; 2939.35,471.74 2964.35,496.74 ; 2939.35,471.74 2939.35,496.74 ; 2939.35,496.74 2964.35,496.74 ; 2941.85,434.24 2961.85,434.24 ; 2961.85,434.24 2971.85,434.24 ; 2961.85,434.24 2994.35,466.74 ; 2964.35,496.74 3091.85,496.74 ; 2971.85,434.24 2976.85,434.24 ; 2976.85,434.24 3154.35,434.24 ; 2976.85,434.24 3009.35,466.74 ; 2994.35,466.74 3009.35,466.74 ; 3009.35,466.74 3121.85,466.74 ; 3091.85,496.74 pad.1@3261.85,496.74 ; 3091.85,496.74 3121.85,466.74 ; 3121.85,466.74 3154.35,434.24 ; 3154.35,434.24 3164.35,434.24 3201.85,434.24 ; 3201.85,434.24 pad.1@3261.85,494.24 ; 3201.85,434.24 3224.35,434.24 3261.85,471.74 pad.1@3261.85,494.24 ; pad.1@3261.85,494.24 pad.1@3264.35,496.74 ; pad.1@3261.85,494.24 pad.1@3261.85,496.74 ; pad.1@3261.85,496.74 pad.1@3264.35,496.74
